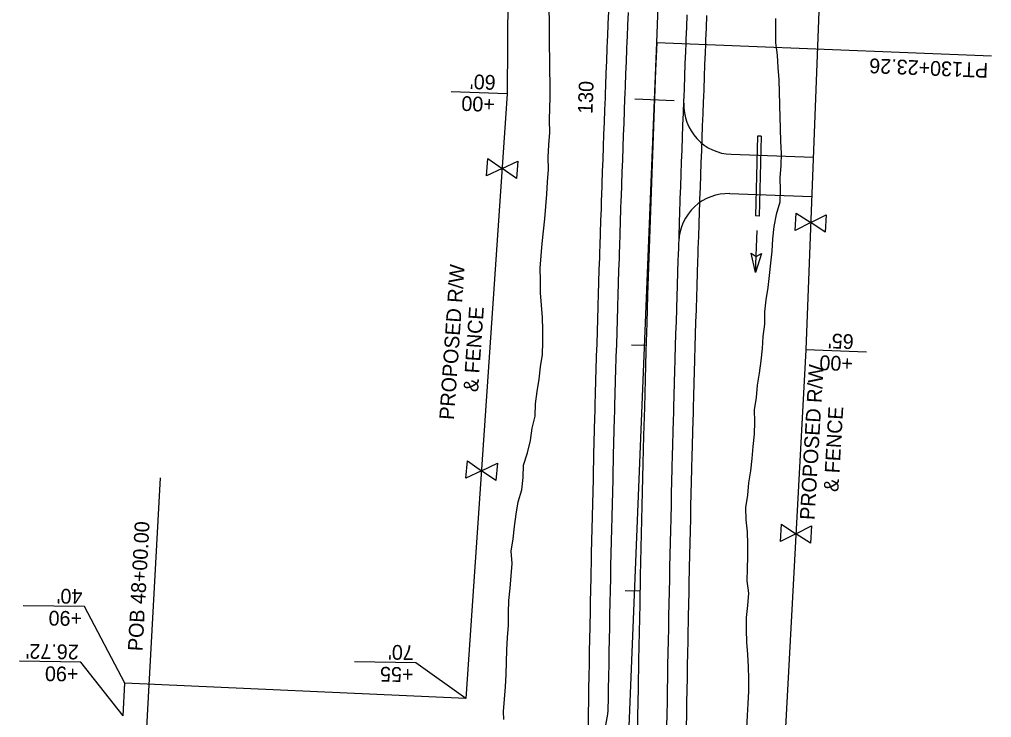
# Model space of a CAD drawing. Extents: x 634057 to 641016, y 287858 to 292331.
# Drawn here: x 634068.8 to 634464.6, y 291613 to 291897 of the extents above; entities that cross this region are included whole.
import ezdxf

# ---------------------------------------------------------------- set-up
doc = ezdxf.new("R2010")
doc.units = 0
for name, color, linetype in [('53', 7, 'Continuous'), ('R_50 Horz Alg PC PI PT', 7, 'Continuous'), ('R_50 Horz Alg Stations', 7, 'Continuous'), ('R_50 Horz Alg Ticks', 7, 'Continuous'), ('R_Drive', 7, 'Continuous'), ('R_Horz Alg', 7, 'Continuous'), ('R_No Plot', 7, 'Continuous'), ('R_Proposed Const Limits', 7, 'Continuous'), ('R_Proposed Road', 7, 'Continuous'), ('R_Proposed Shoulder', 7, 'Continuous'), ('R_ROW', 7, 'Continuous'), ('R_Water', 7, 'Continuous')]:
    doc.layers.add(name, color=color, linetype=linetype)

msp = doc.modelspace()

# ---------------------------------------------------------------- linework, layer by layer
at = {"layer": '53'}
for p, q in [((634267.36, 291866.68), (634244.58, 291867.55)), ((634413.58, 291761.58), (634388.9, 291762.53)), ((634095.25, 291658.09), (634070.3, 291658.47)), ((634111.71, 291626.99), (634095.25, 291658.09)), ((634093.77, 291635.49), (634068.82, 291635.87)), ((634110.99, 291613.73), (634093.77, 291635.49)), ((634230.16, 291635.26), (634205.21, 291635.64)), ((634250.58, 291620.66), (634230.16, 291635.26))]:
    msp.add_line(p, q, dxfattribs=at)
at = {"layer": 'R_50 Horz Alg PC PI PT'}
for points in [[(634313.51, 291522.09), (634328.23, 291887.62)], [(634328.23, 291887.62), (634464.55, 291882.13)], [(634119.52, 291586.5), (634126.28, 291710.5)]]:
    msp.add_lwpolyline(points, dxfattribs=at)
at = {"layer": 'R_50 Horz Alg Ticks'}
for points in [[(634319.32, 291864.69), (634335.31, 291864.08)], [(634317.94, 291764.62), (634323.93, 291764.44)], [(634315.42, 291664.6), (634321.42, 291664.48)]]:
    msp.add_lwpolyline(points, dxfattribs=at)
at = {"layer": 'R_Drive'}
for p, q in [((634358.53, 291842.12), (634391.93, 291840.91)), ((634357.98, 291826.13), (634391.31, 291824.92))]:
    msp.add_line(p, q, dxfattribs=at)
for centre, start, end in [((634359.26, 291862.11), 177.8148, 267.9276), ((634357.26, 291806.14), 87.9276, 178.0956)]:
    msp.add_arc(centre, 20, start, end, dxfattribs=at)
at = {"layer": 'R_Horz Alg'}
msp.add_line((634328.23, 291887.62), (634343.4, 292264.06), dxfattribs=at)
msp.add_arc((645778.1, 291426.39), 11459.16, 177.693224, 181.350269, dxfattribs=at)
at = {"layer": 'R_Proposed Const Limits'}
for points in [[(634266.02, 291612.22), (634265.87, 291615.38), (634266.25, 291620.4), (634266.63, 291625.42), (634267.01, 291630.43), (634267.15, 291635.46), (634267.22, 291640.48), (634267.5, 291645.5), (634267.91, 291650.51), (634267.85, 291655.54), (634268, 291660.56), (634268.58, 291665.57), (634268.95, 291670.59), (634269.37, 291675.61), (634268.95, 291680.64), (634269.76, 291685.64), (634270.4, 291690.65), (634271.05, 291695.66), (634271.8, 291700.67), (634273.37, 291705.65), (634273.89, 291710.66), (634273.95, 291715.68), (634275.66, 291720.66), (634276.83, 291725.66), (634277.54, 291730.66), (634278.8, 291735.65), (634278.85, 291740.67), (634279.57, 291745.67), (634280.45, 291750.66), (634280.97, 291755.67), (634281.71, 291760.67), (634281.94, 291765.68), (634281.92, 291770.7), (634281.78, 291775.73), (634281.38, 291780.76), (634280.92, 291785.8), (634280.88, 291790.82), (634280.86, 291795.84), (634281.18, 291800.85), (634281.67, 291805.86), (634282.18, 291810.87), (634282.66, 291815.87), (634283.14, 291820.88), (634283.54, 291825.88), (634283.84, 291830.89), (634284.16, 291835.9), (634284.08, 291840.93), (634284.36, 291845.94), (634284.73, 291850.95), (634284.6, 291855.98), (634284.79, 291860.99), (634284.82, 291865.27), (634284.83, 291866.01), (634284.8, 291871.03), (634284.75, 291876.06), (634284.7, 291881.08), (634284.65, 291886.11), (634284.6, 291891.13), (634284.56, 291896.13), (634284.47, 291901.14)], [(634376.65, 291897.43), (634376.58, 291892.43), (634376.6, 291887.42), (634377.34, 291882.4), (634377.59, 291877.41), (634378.01, 291872.41), (634378.07, 291867.43), (634378.18, 291862.44), (634378.2, 291861.7), (634378.34, 291857.45), (634378.5, 291852.47), (634378.68, 291847.48), (634378.97, 291842.49), (634378.76, 291837.51), (634378.33, 291832.55), (634378.46, 291827.56), (634378.38, 291822.59), (634376.83, 291817.66), (634375.94, 291812.71), (634375.35, 291807.75), (634375.1, 291802.78), (634374.58, 291797.81), (634374.07, 291792.85), (634373.5, 291787.88), (634372.7, 291782.93), (634372.12, 291777.97), (634372.13, 291772.98), (634371.4, 291768.02), (634371.2, 291763.05), (634370.69, 291758.08), (634369.95, 291753.12), (634369.17, 291748.16), (634368.71, 291743.19), (634367.95, 291738.23), (634368.05, 291733.25), (634367.88, 291728.27), (634367.39, 291723.3), (634366.99, 291718.33), (634366.36, 291713.36), (634365.58, 291708.4), (634365.15, 291703.43), (634364.34, 291698.46), (634364.54, 291693.47), (634365.02, 291688.48), (634365.17, 291683.5), (634365.23, 291678.51), (634365.03, 291673.53), (634364.95, 291668.55), (634365.55, 291663.56), (634365.15, 291658.58), (634364.64, 291653.61), (634364.6, 291648.63), (634364.81, 291643.65), (634365.25, 291638.66), (634365.51, 291633.67), (634365.55, 291628.69), (634365.56, 291623.71), (634365.4, 291618.73), (634365.01, 291613.75), (634364.83, 291608.78)]]:
    msp.add_lwpolyline(points, dxfattribs=at)
at = {"layer": 'R_Proposed Road'}
for points in [[(634308.54, 291617.39), (634308.57, 291619.69), (634308.66, 291624.69), (634308.75, 291629.69), (634308.75, 291629.81), (634308.84, 291634.7), (634308.93, 291639.7), (634309.02, 291644.71), (634309.12, 291649.71), (634309.15, 291651.34), (634309.22, 291654.72), (634309.32, 291659.72), (634309.42, 291664.72), (634309.53, 291669.73), (634309.59, 291672.87), (634309.63, 291674.73), (634309.74, 291679.74), (634309.85, 291684.74), (634309.97, 291689.75), (634310.08, 291694.4), (634310.08, 291694.75), (634310.2, 291699.75), (634310.32, 291704.76), (634310.45, 291709.76), (634310.57, 291714.76), (634310.6, 291715.92), (634310.7, 291719.77), (634310.83, 291724.77), (634310.96, 291729.77), (634311.09, 291734.78), (634311.16, 291737.45), (634311.23, 291739.78), (634311.36, 291744.78), (634311.5, 291749.79), (634311.65, 291754.79), (634311.77, 291758.98), (634311.79, 291759.79), (634311.94, 291764.8), (634312.09, 291769.8), (634312.24, 291774.8), (634312.39, 291779.81), (634312.41, 291780.5), (634312.55, 291784.81), (634312.7, 291789.81), (634312.86, 291794.81), (634313.03, 291799.82), (634313.1, 291802.03), (634313.19, 291804.82), (634313.36, 291809.82), (634313.52, 291814.82), (634313.69, 291819.83), (634313.82, 291823.55), (634313.87, 291824.83), (634314.04, 291829.83), (634314.22, 291834.83), (634314.4, 291839.84), (634314.58, 291844.84), (634314.59, 291845.07), (634314.76, 291849.84), (634314.95, 291854.84), (634315.14, 291859.84), (634315.33, 291864.84), (634315.39, 291866.59), (634315.52, 291869.85), (634315.71, 291874.85), (634315.91, 291879.85), (634316.11, 291884.85), (634316.24, 291888.11), (634316.31, 291889.85), (634316.51, 291894.85), (634316.71, 291899.84)], [(634332.41, 291609.29), (634332.49, 291614.29), (634332.57, 291619.28), (634332.66, 291624.28), (634332.74, 291629.27), (634332.75, 291629.38), (634332.83, 291634.26), (634332.92, 291639.26), (634333.02, 291644.25), (634333.11, 291649.25), (634333.15, 291650.87), (634333.21, 291654.24), (634333.31, 291659.23), (634333.42, 291664.23), (634333.52, 291669.22), (634333.59, 291672.35), (634333.63, 291674.21), (634333.74, 291679.21), (634333.85, 291684.2), (634333.96, 291689.19), (634334.07, 291693.83), (634334.08, 291694.19), (634334.2, 291699.18), (634334.32, 291704.17), (634334.44, 291709.17), (634334.56, 291714.16), (634334.59, 291715.32), (634334.69, 291719.15), (634334.82, 291724.15), (634334.95, 291729.14), (634335.08, 291734.13), (634335.15, 291736.8), (634335.22, 291739.13), (634335.36, 291744.12), (634335.5, 291749.11), (634335.64, 291754.1), (634335.76, 291758.28), (634335.78, 291759.1), (634335.93, 291764.09), (634336.08, 291769.08), (634336.23, 291774.07), (634336.38, 291779.07), (634336.4, 291779.76), (634336.53, 291784.06), (634336.69, 291789.05), (634336.85, 291794.04), (634337.01, 291799.04), (634337.08, 291801.24), (634337.18, 291804.03), (634337.34, 291809.02), (634337.51, 291814.01), (634337.68, 291819), (634337.81, 291822.72), (634337.85, 291824), (634338.03, 291828.99), (634338.2, 291833.98), (634338.38, 291838.97), (634338.56, 291843.96), (634338.57, 291844.19), (634338.75, 291848.95), (634338.93, 291853.94), (634339.12, 291858.94), (634339.31, 291863.93), (634339.38, 291865.67), (634339.5, 291868.92), (634339.7, 291873.91), (634339.89, 291878.9), (634340.09, 291883.89), (634340.22, 291887.14), (634340.29, 291888.88), (634340.49, 291893.88), (634340.69, 291898.88)]]:
    msp.add_lwpolyline(points, dxfattribs=at)
msp.add_arc((634278.54, 291617.89), 30, 266.8777, 359.046, dxfattribs=at)
at = {"layer": 'R_Proposed Shoulder'}
for points in [[(634300.41, 291609.8), (634300.49, 291614.81), (634300.58, 291619.82), (634300.66, 291624.83), (634300.75, 291629.84), (634300.75, 291629.95), (634300.84, 291634.84), (634300.93, 291639.85), (634301.02, 291644.86), (634301.12, 291649.87), (634301.15, 291651.49), (634301.22, 291654.88), (634301.32, 291659.88), (634301.42, 291664.89), (634301.53, 291669.9), (634301.6, 291673.04), (634301.64, 291674.91), (634301.75, 291679.91), (634301.86, 291684.92), (634301.97, 291689.93), (634302.08, 291694.58), (634302.09, 291694.94), (634302.21, 291699.94), (634302.33, 291704.95), (634302.45, 291709.96), (634302.57, 291714.97), (634302.6, 291716.13), (634302.7, 291719.97), (634302.83, 291724.98), (634302.96, 291729.99), (634303.09, 291734.99), (634303.17, 291737.67), (634303.23, 291740), (634303.37, 291745.01), (634303.51, 291750.01), (634303.65, 291755.02), (634303.77, 291759.21), (634303.79, 291760.03), (634303.94, 291765.03), (634304.09, 291770.04), (634304.24, 291775.05), (634304.39, 291780.05), (634304.42, 291780.75), (634304.55, 291785.06), (634304.71, 291790.07), (634304.87, 291795.07), (634305.03, 291800.08), (634305.1, 291802.29), (634305.19, 291805.08), (634305.36, 291810.09), (634305.53, 291815.1), (634305.7, 291820.1), (634305.83, 291823.83), (634305.87, 291825.11), (634306.05, 291830.11), (634306.22, 291835.12), (634306.4, 291840.12), (634306.59, 291845.13), (634306.59, 291845.36), (634306.77, 291850.13), (634306.96, 291855.14), (634307.14, 291860.15), (634307.33, 291865.15), (634307.4, 291866.9), (634307.53, 291870.16), (634307.72, 291875.16), (634307.92, 291880.17), (634308.12, 291885.17), (634308.25, 291888.43), (634308.32, 291890.17), (634308.52, 291895.17), (634308.72, 291900.16)], [(634340.41, 291609.17), (634340.49, 291614.16), (634340.57, 291619.15), (634340.65, 291624.14), (634340.74, 291629.13), (634340.74, 291629.24), (634340.83, 291634.12), (634340.92, 291639.11), (634341.02, 291644.1), (634341.11, 291649.09), (634341.14, 291650.71), (634341.21, 291654.08), (634341.31, 291659.07), (634341.41, 291664.06), (634341.52, 291669.05), (634341.59, 291672.18), (634341.63, 291674.04), (634341.74, 291679.03), (634341.85, 291684.02), (634341.96, 291689.01), (634342.07, 291693.65), (634342.08, 291694), (634342.19, 291698.99), (634342.31, 291703.98), (634342.44, 291708.97), (634342.56, 291713.96), (634342.59, 291715.12), (634342.69, 291718.95), (634342.82, 291723.94), (634342.95, 291728.93), (634343.08, 291733.92), (634343.15, 291736.58), (634343.22, 291738.91), (634343.35, 291743.9), (634343.49, 291748.89), (634343.63, 291753.88), (634343.75, 291758.05), (634343.78, 291758.86), (634343.92, 291763.85), (634344.07, 291768.84), (634344.22, 291773.83), (634344.38, 291778.82), (634344.4, 291779.51), (634344.53, 291783.81), (634344.69, 291788.8), (634344.85, 291793.79), (634345.01, 291798.78), (634345.08, 291800.98), (634345.17, 291803.76), (634345.34, 291808.75), (634345.51, 291813.74), (634345.68, 291818.73), (634345.8, 291822.44), (634345.85, 291823.72), (634346.02, 291828.71), (634346.2, 291833.69), (634346.38, 291838.68), (634346.56, 291843.67), (634346.57, 291843.9), (634346.74, 291848.66), (634346.93, 291853.65), (634347.11, 291858.63), (634347.3, 291863.62), (634347.37, 291865.36), (634347.5, 291868.61), (634347.69, 291873.6), (634347.89, 291878.58), (634348.08, 291883.57), (634348.22, 291886.82), (634348.29, 291888.56), (634348.49, 291893.56), (634348.69, 291898.55)]]:
    msp.add_lwpolyline(points, dxfattribs=at)
at = {"layer": 'R_ROW'}
for p, q in [((634258.9, 291833.39), (634259.51, 291840.43)), ((634259.51, 291840.43), (634265.31, 291836.38)), ((634265.31, 291836.38), (634271.71, 291839.38)), ((634271.71, 291839.38), (634271.1, 291832.33)), ((634265.31, 291836.38), (634258.9, 291833.39)), ((634271.1, 291832.33), (634265.31, 291836.38)), ((634384.64, 291811.12), (634385.01, 291818.18)), ((634385.01, 291818.18), (634390.93, 291814.33)), ((634390.93, 291814.33), (634397.23, 291817.54)), ((634397.23, 291817.54), (634396.86, 291810.48)), ((634390.93, 291814.33), (634384.64, 291811.12)), ((634396.86, 291810.48), (634390.93, 291814.33)), ((634250.56, 291710.4), (634251.17, 291717.45)), ((634251.17, 291717.45), (634256.96, 291713.4)), ((634256.96, 291713.4), (634263.37, 291716.4)), ((634263.37, 291716.4), (634262.76, 291709.35)), ((634256.96, 291713.4), (634250.56, 291710.4)), ((634262.76, 291709.35), (634256.96, 291713.4)), ((634378.64, 291684.57), (634379.01, 291691.64)), ((634379.01, 291691.64), (634384.94, 291687.78)), ((634384.94, 291687.78), (634391.24, 291690.99)), ((634391.24, 291690.99), (634390.87, 291683.92)), ((634384.94, 291687.78), (634378.64, 291684.57)), ((634390.87, 291683.92), (634384.94, 291687.78))]:
    msp.add_line(p, q, dxfattribs=at)
for points in [[(634404.32, 292161.54), (634388.9, 291762.53), (634380.33, 291604.07)], [(634269.02, 292108.03), (634267.36, 291866.68), (634250.58, 291620.66)], [(634110.99, 291613.73), (634111.71, 291626.99)], [(634250.58, 291620.66), (634111.71, 291626.99)]]:
    msp.add_lwpolyline(points, dxfattribs=at)
at = {"layer": 'R_Water'}
for points in [[(634369.24, 291849.52), (634368.39, 291817.03)], [(634370.74, 291849.48), (634369.24, 291849.52)], [(634370.74, 291849.48), (634369.89, 291816.99)], [(634369.89, 291816.99), (634368.39, 291817.03)], [(634368.52, 291794.06), (634369.07, 291811.18)]]:
    msp.add_lwpolyline(points, dxfattribs=at)
msp.add_lwpolyline([(634370.87, 291801.76), (634368.52, 291794.06), (634366.67, 291801.89), (634368.73, 291800.54)], close=True, dxfattribs=at)

# ---------------------------------------------------------------- texts
at = {"layer": '53'}
for s, rotation, p in [("60'  ", 177.8095, (634262.79, 291874.3)), ('+00 ', 177.8095, (634262.45, 291865.31)), ('PROPOSED R/W', 86.0321, (634245.69, 291733.95)), ('& FENCE', 86.0321, (634255.5, 291745.29)), ("65'  ", 177.8095, (634408.55, 291768.84)), ('+00 ', 177.8095, (634408.2, 291759.85)), ('PROPOSED R/W', 86.6174, (634392.47, 291693.23)), ('& FENCE', 86.6174, (634402.16, 291704.67)), ("40'  ", 179.1192, (634094.49, 291665.22)), ('+90 ', 179.1192, (634094.35, 291656.22)), ("26.72'  ", 179.1192, (634093, 291642.62)), ("70'  ", 179.1192, (634229.4, 291642.39)), ('+90 ', 179.1192, (634092.87, 291633.62)), ('+55 ', 179.1192, (634229.26, 291633.39))]:
    msp.add_text(s, height=6, rotation=rotation, dxfattribs=at).set_placement(p)
at = {"layer": 'R_50 Horz Alg PC PI PT'}
for s, rotation, p in [('PT130+23.26', 177.6932, (634463.27, 291879.2)), ('POB 48+00.00', 86.8777, (634118.93, 291639.86))]:
    msp.add_text(s, height=6, rotation=rotation, dxfattribs=at).set_placement(p)
at = {"layer": 'R_50 Horz Alg Stations'}
msp.add_text('130', height=6, rotation=87.8095, dxfattribs=at).set_placement((634302.07, 291858.47))
at = {"layer": 'R_No Plot'}
msp.add_text('+', height=0.1, rotation=87.6932, dxfattribs=at).set_placement((634328.28, 291887.58))
msp.add_text('+', height=0.1, rotation=87.6932, dxfattribs=at).set_placement((634328.28, 291887.58))
msp.add_text('+', height=0.1, rotation=87.6932, dxfattribs=at).set_placement((634328.28, 291887.58))
msp.add_text('+', height=0.1, rotation=87.6932, dxfattribs=at).set_placement((634328.28, 291887.58))
msp.add_text('+', height=0.1, rotation=87.6932, dxfattribs=at).set_placement((634328.28, 291887.58))
msp.add_text('+', height=0.1, rotation=87.6932, dxfattribs=at).set_placement((634328.28, 291887.58))
msp.add_text('+', height=0.1, rotation=87.6932, dxfattribs=at).set_placement((634328.28, 291887.58))
msp.add_text('+', height=0.1, rotation=87.6932, dxfattribs=at).set_placement((634328.28, 291887.58))

doc.saveas('drawing.dxf')
